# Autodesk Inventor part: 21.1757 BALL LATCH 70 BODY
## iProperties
Created: 2007-03
Part Number: 21.1757 BALL LATCH 70 BODY
Document SubType Name: Modeling
Designer: Andy Moles
Material: Steel
Density: 7.85 g/cm^3
Author: Andy Moles
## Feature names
1. Extrusion1
2. Extrusion2
3. Extrusion3
4. Hole1
5. Hole2
